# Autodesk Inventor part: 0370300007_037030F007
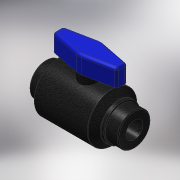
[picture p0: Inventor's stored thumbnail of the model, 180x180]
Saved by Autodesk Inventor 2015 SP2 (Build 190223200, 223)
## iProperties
Created: 2017-06
Part Number: 0370300007_037030F007
Material: PVC-Piping
Description: PLASSON BALL VALVE DN20 FEMALE 3/4" BSPT
Document SubType Name: Modeling
Designer: KIM
Mass: 263.015 g
Surface Area: 292.163 cm^2
Volume: 187.868 cm^3
Density: 1.4 g/cm^3
Appearance: Black Cast
Author: KIM
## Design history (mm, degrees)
derived "03703.ipt"
feature "Solid1::03703.ipt"
tag "TaggingFeature1"
body "Solid1"
other parameters: "d0" = 97, "d3" = 54, "d4" = 17.5, "d5" = 24.117, "d6" = 24.117, "d7" = 17.5, "d8" = 36, "d9" = 14, "d10" = 39.6, "d11" = 15.0485, "d12" = 135 deg, "d14" = 1.20585, "d24" = 14.4702, "d25" = 35.1, "d27" = 14.4702, "d28" = 7.2351, "d29" = 18.9, "d30" = 0, "d32" = 31.83444, "d33" = 3.61755, "d34" = 1.20585, "Rc_" = 24.117, "A_1" = 27, "A_2" = 54, "H_" = 97, "l_" = 17.5, "B_" = 36, "E_" = 1, "d31" = 28.9404
